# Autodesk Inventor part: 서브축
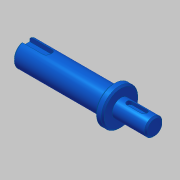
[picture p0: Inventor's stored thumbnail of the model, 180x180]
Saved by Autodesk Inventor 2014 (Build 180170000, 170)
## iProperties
Created: 2018-09
Part Number: 서브축
Document SubType Name: Modeling
Density: 7.86 g/cm^3
Material: 강철, 연강
Appearance: 청록색
Mass: 142.801 g
Surface Area: 54.794 cm^2
Volume: 18.1681 cm^3
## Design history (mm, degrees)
sketch "스케치1"
  geometry: L1 (-18.818, -7)-(-18.818, 7) reference; L2 (-41.331, -13.5)-(-41.331, 13.5) reference; L3 (-46.5, 12.249)-(-46.5, -12.249) reference; L4 (-18.331, 0)-(-106.5, 0); L5 (-18.331, 0)-(-18.331, -6); L6 (-18.331, -6)-(-41.331, -6); L7 (-41.331, -12.5)-(-46.5, -12.5); L8 (-46.5, -8.5)-(-106.5, -8.5); L9 (-106.5, -8.5)-(-106.5, 0); L10 (-46.5, -8.5)-(-46.5, -12.5); L11 (-41.331, -6)-(-41.331, -12.5); 2 further points
  constraints: 17 end point, 5 point on line, 3 parallel, 3 perpendicular, 2 collinear, 1 midpoint
  dimensions: "d0" = 23 distance between parallel lines of L2 L5; "d1" = 12 diameter of L6 L4; "d2" = 25 diameter of L7 L4; "d3" = 17 diameter of L8 L4; "d4" = 60 distance of L8.start L8.end
revolve "회전1" sketch "스케치1" stored, may be unused: angle "d5" = 90 deg
chamfer "모따기1" distance "d6" = 1; stored, may be unused: second distance "d7" = 2, angle "d8" = 45 deg
node "작업 평면1"
sketch "스케치2"
  geometry: L1 (11.5, 5)-(11.5, -5) reference; L2 (-5.5, -2)-(4.5, -2); L3 (4.5, 2)-(-5.5, 2); A1 r 2 centre (4.5, 0) between (4.5, -2) and (4.5, 2); A2 r 2 centre (-5.5, 0) between (-5.5, 2) and (-5.5, -2); 2 further points
  constraints: 4 end point, 4 point on circle, 4 tangent, 2 centre point, 1 horizontal alignment, 1 midpoint, 1 parallel, 1 perpendicular
  dimensions: "d9" = 4 distance between parallel lines of L2 L3; "d10" = 14 dimension on A1 A2; "d11" = 5 distance edge to line of A1 L1
extrude "돌출1" cut sketch "스케치2" distance "d12" = 2.5; taper "d13" = 0 deg
node "작업 평면2"
sketch "스케치3"
  geometry: L1 (-30, -7.5)-(-30, 7.5) reference; L2 (-30, 3)-(-15, 3); L3 (-15, -3)-(-30, -3); A1 r 3 centre (-15, 0) between (-15, -3) and (-15, 3); 2 further points
  constraints: 4 end point, 2 perpendicular, 2 point on circle, 2 point on line, 2 tangent, 1 centre point, 1 horizontal alignment, 1 midpoint
  dimensions: "d14" = 6 distance between parallel lines of L3 L2; "d15" = 18 dimension on A1 L1
extrude "돌출2" cut sketch "스케치3" distance "d16" = 3.5; taper "d17" = 0 deg
node "솔리드1"
node "참조1"
node "참조2"
node "참조3"
